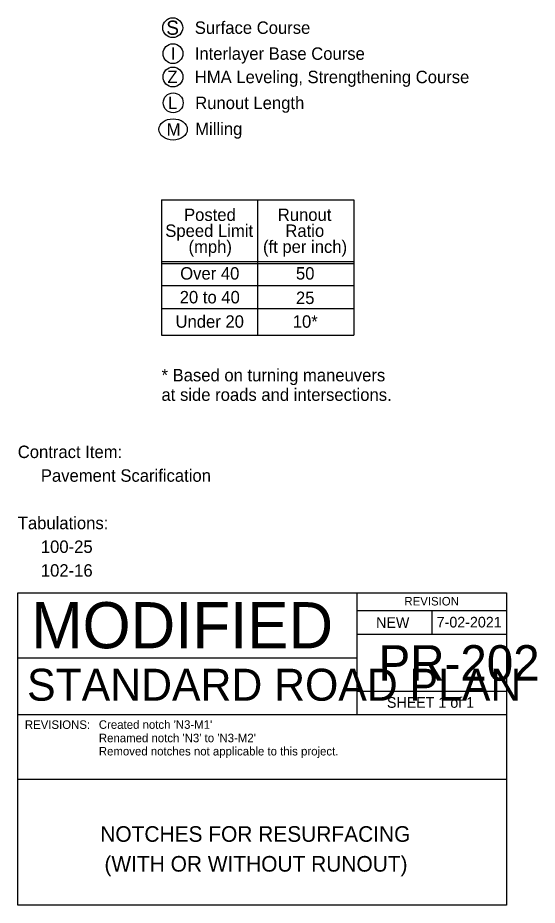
# Model space of a CAD drawing. Extents: x 10133 to 81668, y 2218 to 11018.
# Drawn here: x 16180 to 16911, y 5261 to 6511 of the extents above; entities that cross this region are included whole.
import ezdxf

# ---------------------------------------------------------------- set-up
doc = ezdxf.new("R2010")
doc.units = 0
for name, color, linetype in [('dsnStdBlock', 7, 'Continuous'), ('dsnStdBlockModified', 7, 'Continuous'), ('dsnStdBlockNotModified', 7, 'Continuous'), ('dsnStdBorder', 7, 'Continuous')]:
    doc.layers.add(name, color=color, linetype=linetype)

msp = doc.modelspace()

# ---------------------------------------------------------------- linework, layer by layer
at = {"layer": 'dsnStdBlock'}
for p, q in [((16381.8, 6254.3), (16381.8, 6064)), ((16381.8, 6254.3), (16652.2, 6254.3)), ((16517, 6254.3), (16517, 6064)), ((16652.2, 6254.3), (16652.2, 6064)), ((16381.8, 6167.9), (16652.2, 6167.9)), ((16381.8, 6164.9), (16652.2, 6164.9)), ((16381.8, 6133.8), (16652.2, 6133.8)), ((16381.8, 6101.4), (16652.2, 6101.4)), ((16381.8, 6064), (16652.2, 6064))]:
    msp.add_line(p, q, dxfattribs=at)
for centre in [(16397.6, 6496.9), (16397.9, 6460.4), (16397.9, 6427.5), (16398.2, 6391.1)]:
    msp.add_circle(centre, 14, dxfattribs=at)
msp.add_ellipse((16398.1, 6353.6), major_axis=(-20, 0), ratio=0.749963, dxfattribs=at)
at = {"layer": 'dsnStdBlockModified'}
for p, q in [((16656.6, 5701.2), (16656.6, 5609.8)), ((16656.6, 5676.2), (16867.5, 5676.2)), ((16762.1, 5676.2), (16762.1, 5643)), ((16656.6, 5643), (16867.5, 5643)), ((16656.6, 5609.8), (16656.6, 5529.8)), ((16867.5, 5562), (16656.6, 5562)), ((16179.5, 5529.8), (16867.5, 5529.8))]:
    msp.add_line(p, q, dxfattribs=at)
msp.add_lwpolyline([(16179.5, 5701.2), (16867.5, 5701.2), (16867.5, 5261.2), (16179.5, 5261.2)], close=True, dxfattribs=at)
at = {"layer": 'dsnStdBorder'}
for p, q in [((16179.5, 5609.8), (16656.6, 5609.8)), ((16179.5, 5438.8), (16867.5, 5438.8))]:
    msp.add_line(p, q, dxfattribs=at)

# ---------------------------------------------------------------- texts
at = {"layer": 'dsnStdBlock'}
for s, p in [('Contract Item:', (16179.5, 5890.9)), ('     Pavement Scarification', (16179.5, 5857.5)), ('Tabulations:', (16179.5, 5790.7)), ('     100-25', (16179.5, 5757.3)), ('     102-16', (16179.5, 5723.9))]:
    msp.add_text(s, height=17.5, dxfattribs=at).set_placement(p)
at = {"layer": 'dsnStdBlockModified'}
for s, height, p in [('MODIFIED', 65, (16198.3, 5623)), ('REVISION', 12, (16723.6, 5683.3)), ('NEW', 15, (16683.8, 5651.8)), ('7-02-2021', 15, (16769, 5652.3)), ('PR-202', 50, (16687.2, 5577.4)), ('STANDARD ROAD PLAN', 45.001, (16192.6, 5549.2)), ('SHEET 1 of 1', 15, (16699, 5539.2)), ('NOTCHES FOR RESURFACING', 22, (16295.6, 5350.5)), ('(WITH OR WITHOUT RUNOUT)', 22, (16301.5, 5308.5))]:
    msp.add_text(s, height=height, dxfattribs=at).set_placement(p)
at = {"layer": 'dsnStdBlockNotModified'}
for s, height, p in [('S', 20, (16388.5, 6486.9)), ('Surface Course', 17.5, (16428.6, 6488.2)), ('I', 17.5, (16394.8, 6451.7)), ('Interlayer Base Course', 17.5, (16428.6, 6451.7)), ('Z', 17.5, (16390, 6418.8)), ('HMA Leveling, Strengthening Course', 17.5, (16428.6, 6418.8)), ('L', 17.5, (16391, 6382.3)), ('Runout Length', 17.5, (16429.2, 6382.3)), ('M', 17.5, (16389.1, 6344.8)), ('Milling', 17.5, (16429.2, 6345.8)), ('Posted', 17.5, (16413.5, 6224.8)), ('Runout', 17.5, (16545.4, 6224.8)), ('Speed Limit', 17.5, (16387.1, 6202.3)), ('Ratio', 17.5, (16556.1, 6202.3)), ('(mph)', 17.5, (16419.8, 6179.8)), ('(ft per inch)', 17.5, (16524.6, 6179.8)), ('Over 40', 17.5, (16408.1, 6142.2)), ('50', 17.5, (16571, 6142.2)), ('20 to 40', 17.5, (16407.4, 6108.7)), ('25', 17.5, (16571, 6107.8)), ('Under 20', 17.5, (16401.5, 6074.4)), ('10*', 17.5, (16566.5, 6074.4)), ('* Based on turning maneuvers ', 17.5, (16381.8, 5998.9)), ('at side roads and intersections.', 17.5, (16381.8, 5971.4))]:
    msp.add_text(s, height=height, dxfattribs=at).set_placement(p)
at = {"layer": 'dsnStdBorder'}
for s, p in [('REVISIONS:', (16189.5, 5509.5)), ("Created notch 'N3-M1'", (16293.6, 5509.6)), ("Renamed notch 'N3' to 'N3-M2'", (16293.6, 5490.7)), ('Removed notches not applicable to this project.', (16293.6, 5472.1))]:
    msp.add_text(s, height=12, dxfattribs=at).set_placement(p)

doc.saveas('drawing.dxf')
